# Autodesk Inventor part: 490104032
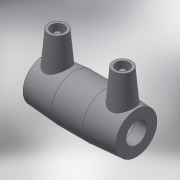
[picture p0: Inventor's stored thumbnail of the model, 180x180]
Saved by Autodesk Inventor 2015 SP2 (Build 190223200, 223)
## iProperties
Created: 2017-06
Part Number: 490104032
Material: Generic
Description: PLASSON COUPLER 32-32
Document SubType Name: Modeling
Designer: KIM
Mass: 55.0731 g
Surface Area: 148.067 cm^2
Volume: 55.0731 cm^3
Density: 1 g/cm^3
Appearance: Default
Author: KIM
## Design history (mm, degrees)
derived "490104.ipt"
feature "Solid1::490104.ipt"
tag "TaggingFeature1"
body "Solid1"
other parameters: "d0" = 88, "d1" = 32, "d2" = 44, "d3" = 42, "d4" = 29.33333, "d5" = 39.6, "d6" = 30.4, "d7" = 32, "d8" = 168 deg, "d10" = 16.8, "d11" = 5.6, "d13" = 88, "d14" = 17.6296, "d15" = 42, "d16" = 42, "d17" = 30.4, "d18" = 32, "d19" = 3.52592, "d20" = 168 deg, "d22" = 41.36, "d23" = 44, "d24" = 40.1192, "d25" = 135 deg, "d26" = 35.2, "d27" = 135 deg, "d29" = 42, "d30" = 14, "d31" = 30.8, "d34" = 5 deg, "d35" = 15, "d39" = 5 deg, "d41" = 4, "d42" = 14, "d43" = 0, "d45" = 4, "d46" = 14, "d47" = 0, "d48" = 3, "d49" = 0, "d50" = 3, "d51" = 0, "d52" = 12.18, "d53" = 3.045, "d_" = 32, "L_" = 88, "L_1" = 42, "D_" = 44, "A_" = 42, "d_2" = 12
